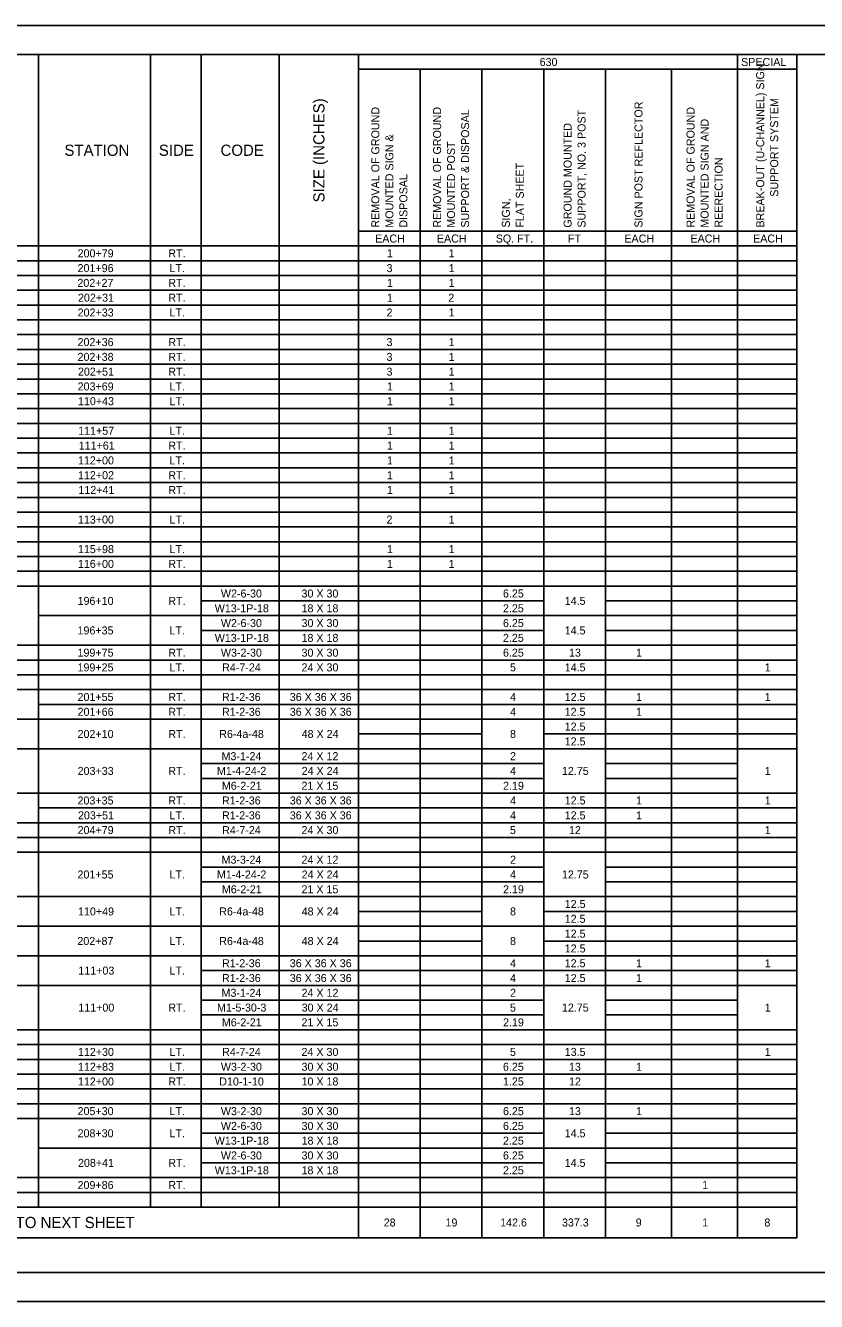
# Model space of a CAD drawing. Extents: x 0 to 34, y 0 to 22.
# Drawn here: x 8.66 to 22.3, y 0 to 22 of the extents above; entities that cross this region are included whole.
import ezdxf

# ---------------------------------------------------------------- set-up
doc = ezdxf.new("R2010")
doc.units = 0
for name, color, linetype in [('SH_Border', 7, 'Continuous'), ('SH_Cut_Line', 7, 'Continuous'), ('SN_P_Cantilever_Overhead', 7, 'Continuous')]:
    doc.layers.add(name, color=color, linetype=linetype)

msp = doc.modelspace()

# ---------------------------------------------------------------- linework, layer by layer
at = {"layer": 'SH_Border'}
msp.add_lwpolyline([(1.5, 21.5), (33.5, 21.5), (33.5, 0.5), (1.5, 0.5)], close=True, dxfattribs=at)
at = {"layer": 'SH_Cut_Line'}
msp.add_lwpolyline([(0, 0), (34, 0), (34, 22), (0, 22)], close=True, dxfattribs=at)
at = {"layer": 'SN_P_Cantilever_Overhead'}
for p, q in [((1.5, 21.5), (21.96, 21.5)), ((8.88, 21.5), (8.88, 1.625)), ((10.815, 21.5), (10.815, 1.625)), ((11.685, 21.5), (11.685, 1.625)), ((13.035, 21.5), (13.035, 1.625)), ((14.4, 21.5), (14.4, 1.1)), ((20.94, 21.5), (20.94, 1.1)), ((21.96, 21.5), (21.96, 1.1)), ((14.4, 21.245), (21.96, 21.245)), ((15.465, 21.245), (15.465, 1.1)), ((16.53, 21.245), (16.53, 1.1)), ((17.595, 21.245), (17.595, 1.1)), ((18.66, 21.245), (18.66, 1.1)), ((19.8, 21.245), (19.8, 1.1)), ((14.4, 18.455), (21.96, 18.455)), ((1.5, 18.2), (21.96, 18.2)), ((1.5, 17.945), (21.96, 17.945)), ((1.5, 17.69), (21.96, 17.69)), ((1.5, 17.435), (21.96, 17.435)), ((1.5, 17.18), (21.96, 17.18)), ((1.5, 16.925), (21.96, 16.925)), ((1.5, 16.67), (21.96, 16.67)), ((1.5, 16.415), (21.96, 16.415)), ((1.5, 16.16), (21.96, 16.16)), ((1.5, 15.905), (21.96, 15.905)), ((1.5, 15.65), (21.96, 15.65)), ((1.5, 15.395), (21.96, 15.395)), ((1.5, 15.14), (21.96, 15.14)), ((1.5, 14.885), (21.96, 14.885)), ((1.5, 14.63), (21.96, 14.63)), ((1.5, 14.375), (21.96, 14.375)), ((1.5, 14.12), (21.96, 14.12)), ((1.5, 13.865), (21.96, 13.865)), ((1.5, 13.61), (21.96, 13.61)), ((1.5, 13.355), (21.96, 13.355)), ((1.5, 13.1), (21.96, 13.1)), ((1.5, 12.845), (21.96, 12.845)), ((1.5, 12.59), (21.96, 12.59)), ((1.5, 12.335), (21.96, 12.335)), ((11.685, 12.08), (17.595, 12.08)), ((18.66, 12.08), (21.96, 12.08)), ((8.88, 11.825), (21.96, 11.825)), ((11.685, 11.57), (17.595, 11.57)), ((18.66, 11.57), (21.96, 11.57)), ((1.5, 11.315), (21.96, 11.315)), ((1.5, 11.06), (21.96, 11.06)), ((1.5, 10.805), (21.96, 10.805)), ((1.5, 10.55), (21.96, 10.55)), ((8.88, 10.295), (21.96, 10.295)), ((1.5, 10.04), (21.96, 10.04)), ((14.4, 9.785), (16.53, 9.785)), ((17.595, 9.785), (21.96, 9.785)), ((1.5, 9.53), (21.96, 9.53)), ((11.685, 9.275), (17.595, 9.275)), ((18.66, 9.275), (20.94, 9.275)), ((11.685, 9.02), (17.595, 9.02)), ((18.66, 9.02), (20.94, 9.02)), ((1.5, 8.765), (21.96, 8.765)), ((8.88, 8.51), (21.96, 8.51)), ((1.5, 8.255), (21.96, 8.255)), ((1.5, 8), (21.96, 8)), ((1.5, 7.745), (21.96, 7.745)), ((11.685, 7.49), (17.595, 7.49)), ((18.66, 7.49), (21.96, 7.49)), ((11.685, 7.235), (17.595, 7.235)), ((18.66, 7.235), (21.96, 7.235)), ((1.5, 6.98), (21.96, 6.98)), ((14.4, 6.725), (16.53, 6.725)), ((17.595, 6.725), (21.96, 6.725)), ((1.5, 6.47), (21.96, 6.47)), ((14.4, 6.215), (16.53, 6.215)), ((17.595, 6.215), (21.96, 6.215)), ((1.5, 5.96), (21.96, 5.96)), ((11.685, 5.705), (21.96, 5.705)), ((1.5, 5.45), (21.96, 5.45)), ((11.685, 5.195), (17.595, 5.195)), ((18.66, 5.195), (20.94, 5.195)), ((11.685, 4.94), (17.595, 4.94)), ((18.66, 4.94), (20.94, 4.94)), ((1.5, 4.685), (21.96, 4.685)), ((1.5, 4.43), (21.96, 4.43)), ((1.5, 4.175), (21.96, 4.175)), ((1.5, 3.92), (21.96, 3.92)), ((1.5, 3.665), (21.96, 3.665)), ((1.5, 3.41), (21.96, 3.41)), ((1.5, 3.155), (21.96, 3.155)), ((11.685, 2.9), (17.595, 2.9)), ((18.66, 2.9), (21.96, 2.9)), ((8.88, 2.645), (21.96, 2.645)), ((11.685, 2.39), (17.595, 2.39)), ((18.66, 2.39), (21.96, 2.39)), ((1.5, 2.135), (21.96, 2.135)), ((1.5, 1.88), (21.96, 1.88)), ((1.5, 1.625), (21.96, 1.625)), ((1.5, 1.1), (21.96, 1.1))]:
    msp.add_line(p, q, dxfattribs=at)

# ---------------------------------------------------------------- texts
for s, height, p in [('630', 0.138, (17.525, 21.303)), ('SPECIAL', 0.138, (21, 21.303)), ('STATION', 0.1932, (9.328, 19.753)), ('SIDE', 0.1932, (10.957, 19.753)), ('CODE', 0.1932, (12.021, 19.753)), ('EACH', 0.138, (14.688, 18.258)), ('EACH', 0.138, (15.753, 18.258)), ('SQ. FT.', 0.138, (16.767, 18.258)), ('FT', 0.138, (18.013, 18.258)), ('EACH', 0.138, (18.986, 18.258)), ('EACH', 0.138, (20.126, 18.258)), ('EACH', 0.138, (21.206, 18.258)), ('200+79', 0.138, (9.556, 18.003)), ('RT.', 0.138, (11.12, 18.003)), ('1', 0.138, (14.891, 18.003)), ('1', 0.138, (15.956, 18.003)), ('201+96', 0.138, (9.555, 17.748)), ('LT.', 0.138, (11.14, 17.748)), ('3', 0.138, (14.884, 17.748)), ('1', 0.138, (15.956, 17.748)), ('202+27', 0.138, (9.552, 17.494)), ('RT.', 0.138, (11.12, 17.494)), ('1', 0.138, (14.891, 17.494)), ('1', 0.138, (15.956, 17.494)), ('202+31', 0.138, (9.562, 17.238)), ('RT.', 0.138, (11.12, 17.238)), ('1', 0.138, (14.891, 17.238)), ('2', 0.138, (15.949, 17.238)), ('202+33', 0.138, (9.556, 16.983)), ('LT.', 0.138, (11.14, 16.983)), ('2', 0.138, (14.884, 16.983)), ('1', 0.138, (15.956, 16.983)), ('202+36', 0.138, (9.555, 16.473)), ('RT.', 0.138, (11.12, 16.473)), ('3', 0.138, (14.884, 16.473)), ('1', 0.138, (15.956, 16.473)), ('202+38', 0.138, (9.555, 16.218)), ('RT.', 0.138, (11.12, 16.218)), ('3', 0.138, (14.884, 16.218)), ('1', 0.138, (15.956, 16.218)), ('202+51', 0.138, (9.562, 15.963)), ('RT.', 0.138, (11.12, 15.963)), ('3', 0.138, (14.884, 15.963)), ('1', 0.138, (15.956, 15.963)), ('203+69', 0.138, (9.556, 15.708)), ('LT.', 0.138, (11.14, 15.708)), ('1', 0.138, (14.891, 15.708)), ('1', 0.138, (15.956, 15.708)), ('110+43', 0.138, (9.562, 15.454)), ('LT.', 0.138, (11.14, 15.454)), ('1', 0.138, (14.891, 15.454)), ('1', 0.138, (15.956, 15.454)), ('111+57', 0.138, (9.565, 14.944)), ('LT.', 0.138, (11.14, 14.944)), ('1', 0.138, (14.891, 14.944)), ('1', 0.138, (15.956, 14.944)), ('111+61', 0.138, (9.575, 14.688)), ('RT.', 0.138, (11.12, 14.688)), ('1', 0.138, (14.891, 14.688)), ('1', 0.138, (15.956, 14.688)), ('112+00', 0.138, (9.561, 14.433)), ('LT.', 0.138, (11.14, 14.433)), ('1', 0.138, (14.891, 14.433)), ('1', 0.138, (15.956, 14.433)), ('112+02', 0.138, (9.562, 14.178)), ('RT.', 0.138, (11.12, 14.178)), ('1', 0.138, (14.891, 14.178)), ('1', 0.138, (15.956, 14.178)), ('112+41', 0.138, (9.569, 13.923)), ('RT.', 0.138, (11.12, 13.923)), ('1', 0.138, (14.891, 13.923)), ('1', 0.138, (15.956, 13.923)), ('113+00', 0.138, (9.561, 13.413)), ('LT.', 0.138, (11.14, 13.413)), ('2', 0.138, (14.884, 13.413)), ('1', 0.138, (15.956, 13.413)), ('115+98', 0.138, (9.561, 12.903)), ('LT.', 0.138, (11.14, 12.903)), ('1', 0.138, (14.891, 12.903)), ('1', 0.138, (15.956, 12.903)), ('116+00', 0.138, (9.561, 12.649)), ('RT.', 0.138, (11.12, 12.649)), ('1', 0.138, (14.891, 12.649)), ('1', 0.138, (15.956, 12.649)), ('196+10', 0.138, (9.555, 12.011)), ('RT.', 0.138, (11.12, 12.011)), ('W2-6-30', 0.138, (12.027, 12.138)), ('30 X 30', 0.138, (13.418, 12.138)), ('6.25', 0.138, (16.892, 12.138)), ('14.5', 0.138, (17.957, 12.011)), ('W13-1P-18', 0.138, (11.921, 11.883)), ('18 X 18', 0.138, (13.418, 11.883)), ('2.25', 0.138, (16.892, 11.883)), ('W2-6-30', 0.138, (12.027, 11.628)), ('30 X 30', 0.138, (13.418, 11.628)), ('6.25', 0.138, (16.892, 11.628)), ('196+35', 0.138, (9.554, 11.501)), ('LT.', 0.138, (11.14, 11.501)), ('W13-1P-18', 0.138, (11.921, 11.373)), ('18 X 18', 0.138, (13.418, 11.373)), ('2.25', 0.138, (16.892, 11.373)), ('14.5', 0.138, (17.957, 11.501)), ('199+75', 0.138, (9.554, 11.118)), ('RT.', 0.138, (11.12, 11.118)), ('W3-2-30', 0.138, (12.027, 11.118)), ('30 X 30', 0.138, (13.418, 11.118)), ('6.25', 0.138, (16.892, 11.118)), ('13', 0.138, (18.031, 11.118)), ('1', 0.138, (19.188, 11.118)), ('199+25', 0.138, (9.554, 10.864)), ('LT.', 0.138, (11.14, 10.864)), ('R4-7-24', 0.138, (12.048, 10.864)), ('24 X 30', 0.138, (13.418, 10.864)), ('5', 0.138, (17.013, 10.864)), ('14.5', 0.138, (17.957, 10.864)), ('1', 0.138, (21.408, 10.864)), ('201+55', 0.138, (9.554, 10.354)), ('RT.', 0.138, (11.12, 10.354)), ('R1-2-36', 0.138, (12.046, 10.354)), ('36 X 36 X 36', 0.138, (13.215, 10.354)), ('4', 0.138, (17.015, 10.354)), ('12.5', 0.138, (17.957, 10.354)), ('1', 0.138, (19.188, 10.354)), ('1', 0.138, (21.408, 10.354)), ('201+66', 0.138, (9.555, 10.098)), ('RT.', 0.138, (11.12, 10.098)), ('R1-2-36', 0.138, (12.046, 10.098)), ('36 X 36 X 36', 0.138, (13.215, 10.098)), ('4', 0.138, (17.015, 10.098)), ('12.5', 0.138, (17.957, 10.098)), ('1', 0.138, (19.188, 10.098)), ('12.5', 0.138, (17.957, 9.843)), ('202+10', 0.138, (9.555, 9.716)), ('RT.', 0.138, (11.12, 9.716)), ('R6-4a-48', 0.138, (11.998, 9.716)), ('48 X 24', 0.138, (13.42, 9.716)), ('8', 0.138, (17.014, 9.716)), ('12.5', 0.138, (17.957, 9.588)), ('M3-1-24', 0.138, (12.038, 9.333)), ('24 X 12', 0.138, (13.418, 9.333)), ('2', 0.138, (17.014, 9.333)), ('203+33', 0.138, (9.556, 9.079)), ('RT.', 0.138, (11.12, 9.079)), ('M1-4-24-2', 0.138, (11.959, 9.079)), ('24 X 24', 0.138, (13.42, 9.079)), ('4', 0.138, (17.015, 9.079)), ('12.75', 0.138, (17.909, 9.079)), ('1', 0.138, (21.408, 9.079)), ('M6-2-21', 0.138, (12.044, 8.823)), ('21 X 15', 0.138, (13.417, 8.823)), ('2.19', 0.138, (16.894, 8.823)), ('203+35', 0.138, (9.554, 8.569)), ('RT.', 0.138, (11.12, 8.569)), ('R1-2-36', 0.138, (12.046, 8.569)), ('36 X 36 X 36', 0.138, (13.215, 8.569)), ('4', 0.138, (17.015, 8.569)), ('12.5', 0.138, (17.957, 8.569)), ('1', 0.138, (19.188, 8.569)), ('1', 0.138, (21.408, 8.569)), ('203+51', 0.138, (9.562, 8.313)), ('LT.', 0.138, (11.14, 8.313)), ('R1-2-36', 0.138, (12.046, 8.313)), ('36 X 36 X 36', 0.138, (13.215, 8.313)), ('4', 0.138, (17.015, 8.313)), ('12.5', 0.138, (17.957, 8.313)), ('1', 0.138, (19.188, 8.313)), ('204+79', 0.138, (9.556, 8.059)), ('RT.', 0.138, (11.12, 8.059)), ('R4-7-24', 0.138, (12.048, 8.059)), ('24 X 30', 0.138, (13.418, 8.059)), ('5', 0.138, (17.013, 8.059)), ('12', 0.138, (18.031, 8.059)), ('1', 0.138, (21.408, 8.059)), ('M3-3-24', 0.138, (12.038, 7.548)), ('24 X 12', 0.138, (13.418, 7.548)), ('2', 0.138, (17.014, 7.548)), ('201+55', 0.138, (9.554, 7.293)), ('LT.', 0.138, (11.14, 7.293)), ('M1-4-24-2', 0.138, (11.959, 7.293)), ('24 X 24', 0.138, (13.42, 7.293)), ('4', 0.138, (17.015, 7.293)), ('12.75', 0.138, (17.909, 7.293)), ('M6-2-21', 0.138, (12.044, 7.038)), ('21 X 15', 0.138, (13.417, 7.038)), ('2.19', 0.138, (16.894, 7.038)), ('12.5', 0.138, (17.957, 6.784)), ('110+49', 0.138, (9.563, 6.656)), ('LT.', 0.138, (11.14, 6.656)), ('R6-4a-48', 0.138, (11.998, 6.656)), ('48 X 24', 0.138, (13.42, 6.656)), ('8', 0.138, (17.014, 6.656)), ('12.5', 0.138, (17.957, 6.529)), ('12.5', 0.138, (17.957, 6.273)), ('202+87', 0.138, (9.552, 6.146)), ('LT.', 0.138, (11.14, 6.146)), ('R6-4a-48', 0.138, (11.998, 6.146)), ('48 X 24', 0.138, (13.42, 6.146)), ('8', 0.138, (17.014, 6.146)), ('12.5', 0.138, (17.957, 6.018)), ('111+03', 0.138, (9.568, 5.636)), ('LT.', 0.138, (11.14, 5.636)), ('R1-2-36', 0.138, (12.046, 5.763)), ('36 X 36 X 36', 0.138, (13.215, 5.763)), ('4', 0.138, (17.015, 5.763)), ('12.5', 0.138, (17.957, 5.763)), ('1', 0.138, (19.188, 5.763)), ('1', 0.138, (21.408, 5.763)), ('R1-2-36', 0.138, (12.046, 5.508)), ('36 X 36 X 36', 0.138, (13.215, 5.508)), ('4', 0.138, (17.015, 5.508)), ('12.5', 0.138, (17.957, 5.508)), ('1', 0.138, (19.188, 5.508)), ('M3-1-24', 0.138, (12.038, 5.253)), ('24 X 12', 0.138, (13.418, 5.253)), ('2', 0.138, (17.014, 5.253)), ('111+00', 0.138, (9.568, 4.998)), ('RT.', 0.138, (11.12, 4.998)), ('M1-5-30-3', 0.138, (11.96, 4.998)), ('30 X 24', 0.138, (13.42, 4.998)), ('5', 0.138, (17.013, 4.998)), ('12.75', 0.138, (17.909, 4.998)), ('1', 0.138, (21.408, 4.998)), ('M6-2-21', 0.138, (12.044, 4.744)), ('21 X 15', 0.138, (13.417, 4.744)), ('2.19', 0.138, (16.894, 4.744)), ('112+30', 0.138, (9.561, 4.234)), ('LT.', 0.138, (11.14, 4.234)), ('R4-7-24', 0.138, (12.048, 4.234)), ('24 X 30', 0.138, (13.418, 4.234)), ('5', 0.138, (17.013, 4.234)), ('13.5', 0.138, (17.957, 4.234)), ('1', 0.138, (21.408, 4.234)), ('112+83', 0.138, (9.562, 3.978)), ('LT.', 0.138, (11.14, 3.978)), ('W3-2-30', 0.138, (12.027, 3.978)), ('30 X 30', 0.138, (13.418, 3.978)), ('6.25', 0.138, (16.892, 3.978)), ('13', 0.138, (18.031, 3.978)), ('1', 0.138, (19.188, 3.978)), ('112+00', 0.138, (9.561, 3.724)), ('RT.', 0.138, (11.12, 3.724)), ('D10-1-10', 0.138, (11.998, 3.724)), ('10 X 18', 0.138, (13.418, 3.724)), ('1.25', 0.138, (16.892, 3.724)), ('12', 0.138, (18.031, 3.724)), ('205+30', 0.138, (9.555, 3.213)), ('LT.', 0.138, (11.14, 3.213)), ('W3-2-30', 0.138, (12.027, 3.213)), ('30 X 30', 0.138, (13.418, 3.213)), ('6.25', 0.138, (16.892, 3.213)), ('13', 0.138, (18.031, 3.213)), ('1', 0.138, (19.188, 3.213)), ('W2-6-30', 0.138, (12.027, 2.958)), ('30 X 30', 0.138, (13.418, 2.958)), ('6.25', 0.138, (16.892, 2.958)), ('208+30', 0.138, (9.555, 2.831)), ('LT.', 0.138, (11.14, 2.831)), ('14.5', 0.138, (17.957, 2.831)), ('W13-1P-18', 0.138, (11.921, 2.704)), ('18 X 18', 0.138, (13.418, 2.704)), ('2.25', 0.138, (16.892, 2.704)), ('208+41', 0.138, (9.562, 2.321)), ('RT.', 0.138, (11.12, 2.321)), ('W2-6-30', 0.138, (12.027, 2.449)), ('30 X 30', 0.138, (13.418, 2.449)), ('6.25', 0.138, (16.892, 2.449)), ('14.5', 0.138, (17.957, 2.321)), ('W13-1P-18', 0.138, (11.921, 2.193)), ('18 X 18', 0.138, (13.418, 2.193)), ('2.25', 0.138, (16.892, 2.193)), ('209+86', 0.138, (9.555, 1.938)), ('RT.', 0.138, (11.12, 1.938)), ('1', 0.138, (20.328, 1.938)), ('SUBTOTALS CARRIED TO NEXT SHEET', 0.1932, (5.644, 1.266)), ('28', 0.138, (14.835, 1.293)), ('19', 0.138, (15.901, 1.293)), ('142.6', 0.138, (16.844, 1.293)), ('337.3', 0.138, (17.91, 1.293)), ('9', 0.138, (19.182, 1.293)), ('1', 0.138, (20.328, 1.293)), ('8', 0.138, (21.401, 1.293))]:
    msp.add_text(s, height=height, dxfattribs=at).set_placement(p)
for s, height, p in [('BREAK-OUT (U-CHANNEL) SIGN ', 0.138, (21.398, 18.517)), ('SIZE (INCHES)', 0.1932, (13.814, 18.95)), ('SIGN POST REFLECTOR', 0.138, (19.299, 18.515)), ('SUPPORT SYSTEM', 0.138, (21.64, 19.048)), ('REMOVAL OF GROUND ', 0.138, (14.76, 18.515)), ('REMOVAL OF GROUND', 0.138, (15.825, 18.515)), ('SUPPORT & DISPOSAL', 0.138, (16.308, 18.515)), ('SUPPORT, NO. 3 POST', 0.138, (18.317, 18.515)), ('REMOVAL OF GROUND ', 0.138, (20.197, 18.515)), ('GROUND MOUNTED', 0.138, (18.076, 18.515)), ('MOUNTED SIGN AND ', 0.138, (20.439, 18.515)), ('MOUNTED SIGN &', 0.138, (15.002, 18.515)), ('MOUNTED POST', 0.138, (16.066, 18.515)), ('FLAT SHEET', 0.138, (17.252, 18.515)), ('REERECTION', 0.138, (20.68, 18.515)), ('DISPOSAL', 0.138, (15.243, 18.515)), ('SIGN, ', 0.138, (17.011, 18.515))]:
    msp.add_text(s, height=height, rotation=90, dxfattribs=at).set_placement(p)

doc.saveas('drawing.dxf')
